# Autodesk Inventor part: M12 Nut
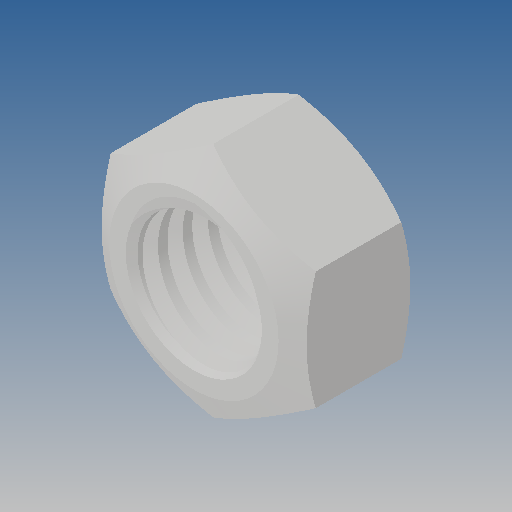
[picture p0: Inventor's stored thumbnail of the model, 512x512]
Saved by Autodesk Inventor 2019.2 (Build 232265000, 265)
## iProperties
Created: 2015-08
Part Number: M12 Nut
Material: Ogólny
Document SubType Name: Modeling
Designer: CADENGINEERING4
Density: 1 g/cm^3
Appearance: Domyślna
Author: CADENGINEERING4
Revision Number: ÈÎºÎ
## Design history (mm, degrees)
feature "ÇÐ³ý-É¨Ãè2"
node "Bryła1"
